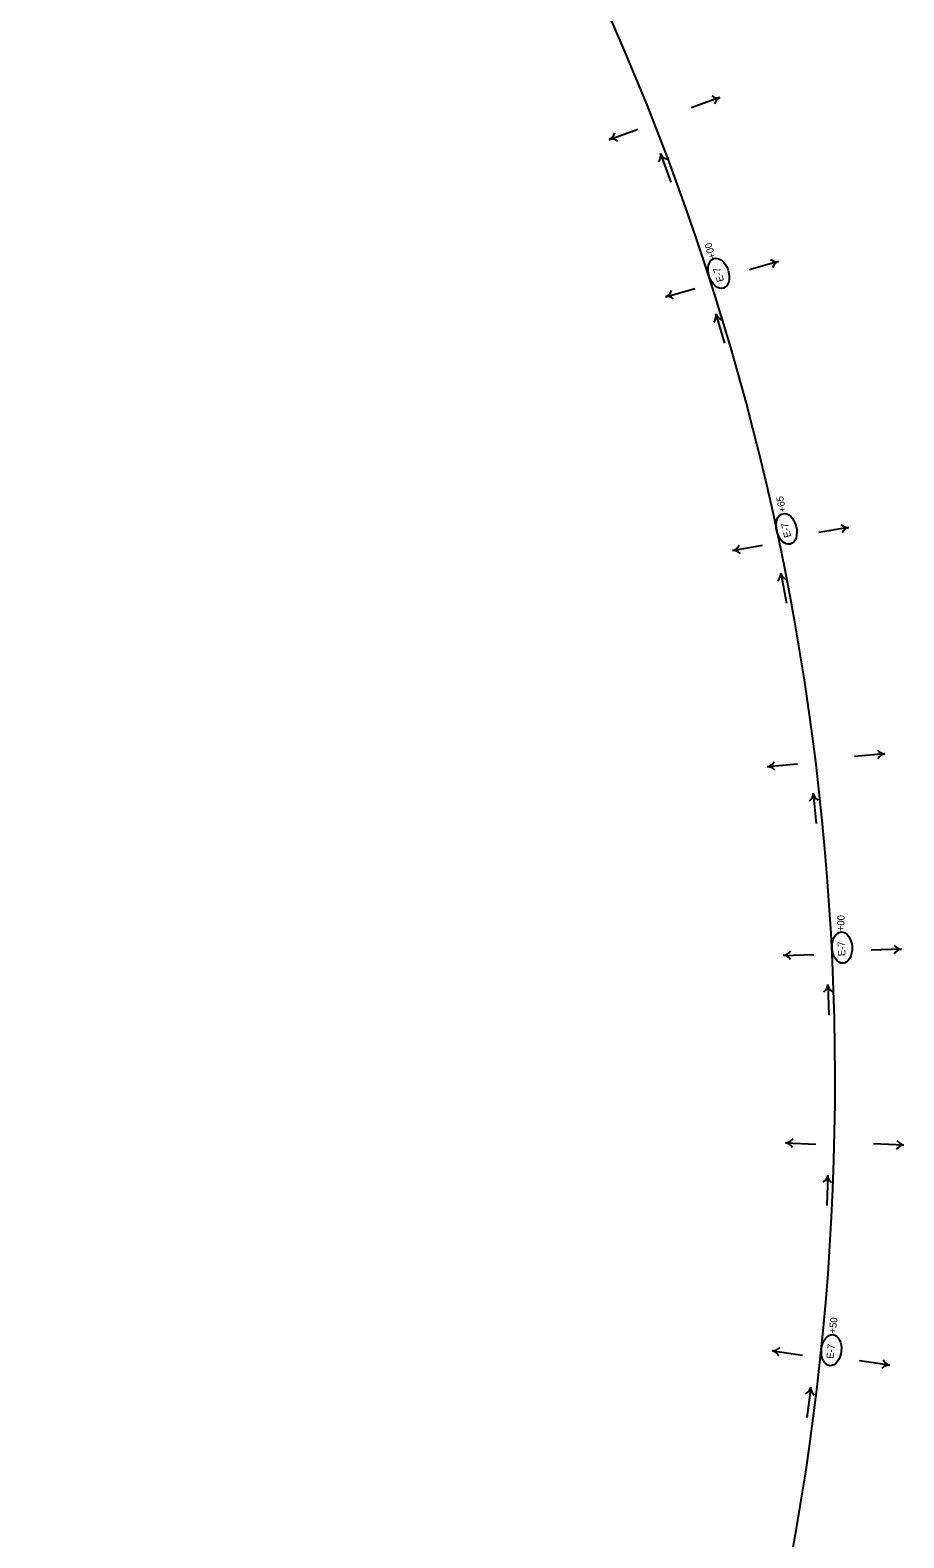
# Model space of a CAD drawing. Extents: x 669236 to 673912, y 735758 to 754788.
# Drawn here: x 673146 to 673912, y 749484 to 750806 of the extents above; entities that cross this region are included whole.
import ezdxf

# ---------------------------------------------------------------- set-up
doc = ezdxf.new("R2010")
doc.units = 0
for name, color, linetype in [('Default', 7, 'Continuous'), ('R_Erosion_2', 7, 'Continuous'), ('R_Flow Arrows', 7, 'Continuous')]:
    doc.layers.add(name, color=color, linetype=linetype)

msp = doc.modelspace()

# ---------------------------------------------------------------- linework, layer by layer
at = {"layer": 'Default'}
msp.add_arc((671559.6, 749886.2), 2291.8, 325.1701, 46.1906, dxfattribs=at)
at = {"layer": 'R_Erosion_2'}
for centre, major_axis in [((673749.4, 750592.5), (-4.2, 13)), ((673808.8, 750368.6), (-3.3, 13.3)), ((673857.5, 750001.7), (-0.8, 13.7)), ((673848.1, 749648.9), (1.3, 13.6))]:
    msp.add_ellipse(centre, major_axis=major_axis, ratio=0.638788, dxfattribs=at)
at = {"layer": 'R_Flow Arrows'}
for p, q in [((673750.3, 750746.6), (673725.2, 750737.7)), ((673653.6, 750709.9), (673678.6, 750718.8)), ((673698.4, 750697.2), (673707.5, 750672.3)), ((673801.7, 750603), (673776.1, 750595.6)), ((673703, 750572.1), (673728.5, 750579.4)), ((673746.9, 750556.8), (673754.5, 750531.3)), ((673863.1, 750369.9), (673837, 750365.3)), ((673761.7, 750349.6), (673787.9, 750354.2)), ((673803.8, 750329.7), (673808.7, 750303.6)), ((673894.9, 750171.5), (673868.4, 750169.2)), ((673792.1, 750160.3), (673818.5, 750162.6)), ((673832.2, 750136.8), (673834.8, 750110.3)), ((673909.4, 750000.2), (673882.9, 749999.4)), ((673806.1, 749994.8), (673832.7, 749995.6)), ((673844.9, 749969.1), (673845.9, 749942.5)), ((673808, 749830.6), (673834.6, 749829.5)), ((673911.4, 749828.6), (673884.9, 749829.7)), ((673844.9, 749802.2), (673844, 749775.6)), ((673796.4, 749648.4), (673822.7, 749644.6)), ((673899.1, 749635.7), (673872.8, 749639.6)), ((673830.1, 749616.3), (673826.5, 749590))]:
    msp.add_line(p, q, dxfattribs=at)
for centre, major_axis, start_param, end_param in [((673744, 750765.7), (6.7, -19), 5.662936, 6.259934), ((673757.3, 750727.7), (-6.7, 19), 0.023252, 0.620249), ((673646.6, 750728.8), (6.7, -19), 0.023252, 0.620249), ((673659.9, 750690.8), (-6.7, 19), 5.662936, 6.259934), ((673679.3, 750690.8), (18.9, 6.9), 5.662936, 6.259934), ((673717.2, 750704.4), (-18.9, -6.9), 0.023252, 0.620249), ((673796.5, 750622.4), (5.6, -19.4), 5.662936, 6.259934), ((673807.5, 750583.7), (-5.6, 19.4), 0.023252, 0.620249), ((673708.1, 750552.6), (-5.6, 19.4), 5.662936, 6.259934), ((673697.1, 750591.4), (5.6, -19.4), 0.023252, 0.620249), ((673727.5, 750551.4), (19.3, 5.8), 5.662936, 6.259934), ((673766.2, 750562.8), (-19.3, -5.8), 0.023252, 0.620249), ((673860, 750389.8), (3.5, -19.9), 5.662936, 6.259934), ((673866.9, 750350.1), (-3.5, 19.9), 0.023252, 0.620249), ((673758, 750369.4), (3.5, -19.9), 0.023252, 0.620249), ((673764.8, 750329.7), (-3.5, 19.9), 5.662936, 6.259934), ((673783.9, 750326.5), (19.8, 3.7), 5.662936, 6.259934), ((673823.6, 750333.7), (-19.8, -3.7), 0.023252, 0.620249), ((673893.6, 750191.6), (1.7, -20.1), 5.662936, 6.259934), ((673896.9, 750151.4), (-1.7, 20.1), 0.023252, 0.620249), ((673793.4, 750140.2), (-1.7, 20.1), 5.662936, 6.259934), ((673790.1, 750180.3), (1.7, -20.1), 0.023252, 0.620249), ((673812.1, 750135.3), (20.1, 1.9), 5.662936, 6.259934), ((673852.3, 750138.9), (-20.1, -1.9), 0.023252, 0.620249), ((673805.3, 750015), (0.6, -20.2), 0.023252, 0.620249), ((673909.3, 750020.4), (0.6, -20.2), 5.662936, 6.259934), ((673910.3, 749980.1), (-0.6, 20.2), 0.023252, 0.620249), ((673806.3, 749974.7), (-0.6, 20.2), 5.662936, 6.259934), ((673824.8, 749968.7), (20.1, 0.8), 5.662936, 6.259934), ((673865.1, 749970.1), (-20.1, -0.8), 0.023252, 0.620249), ((673806.8, 749810.5), (0.8, 20.1), 5.662936, 6.259934), ((673808.6, 749850.7), (-0.8, -20.1), 0.023252, 0.620249), ((673910.9, 749808.5), (0.8, 20.1), 0.023252, 0.620249), ((673912.7, 749848.8), (-0.8, -20.1), 5.662936, 6.259934), ((673824.8, 749803.3), (20.2, -0.7), 5.662936, 6.259934), ((673865, 749801.8), (-20.2, 0.7), 0.023252, 0.620249), ((673793.1, 749628.6), (2.9, 19.9), 5.662936, 6.259934), ((673799.1, 749668.4), (-2.9, -19.9), 0.023252, 0.620249), ((673896.4, 749615.7), (2.9, 19.9), 0.023252, 0.620249), ((673902.4, 749655.6), (-2.9, -19.9), 5.662936, 6.259934), ((673810.2, 749619.5), (20, -2.8), 5.662936, 6.259934), ((673850.1, 749613.8), (-20, 2.8), 0.023252, 0.620249)]:
    msp.add_ellipse(centre, major_axis=major_axis, ratio=0.5625, start_param=start_param, end_param=end_param, dxfattribs=at)

# ---------------------------------------------------------------- texts
at = {"layer": 'R_Erosion_2'}
for s, rotation, p in [('+00', 107.1312, (673746.9, 750606.4)), ('E-7', 107.988, (673754.2, 750586.1)), ('+65', 101.1802, (673808.5, 750383.8)), ('E-7', 103.7286, (673813.1, 750361.8)), ('+00', 87.9779, (673859.2, 750015.9)), ('E-7', 93.2338, (673860.5, 749994.3)), ('+50', 83.6023, (673852, 749663.2)), ('E-7', 84.5854, (673850, 749641.1))]:
    msp.add_text(s, height=6.25, rotation=rotation, dxfattribs=at).set_placement(p)

doc.saveas('drawing.dxf')
